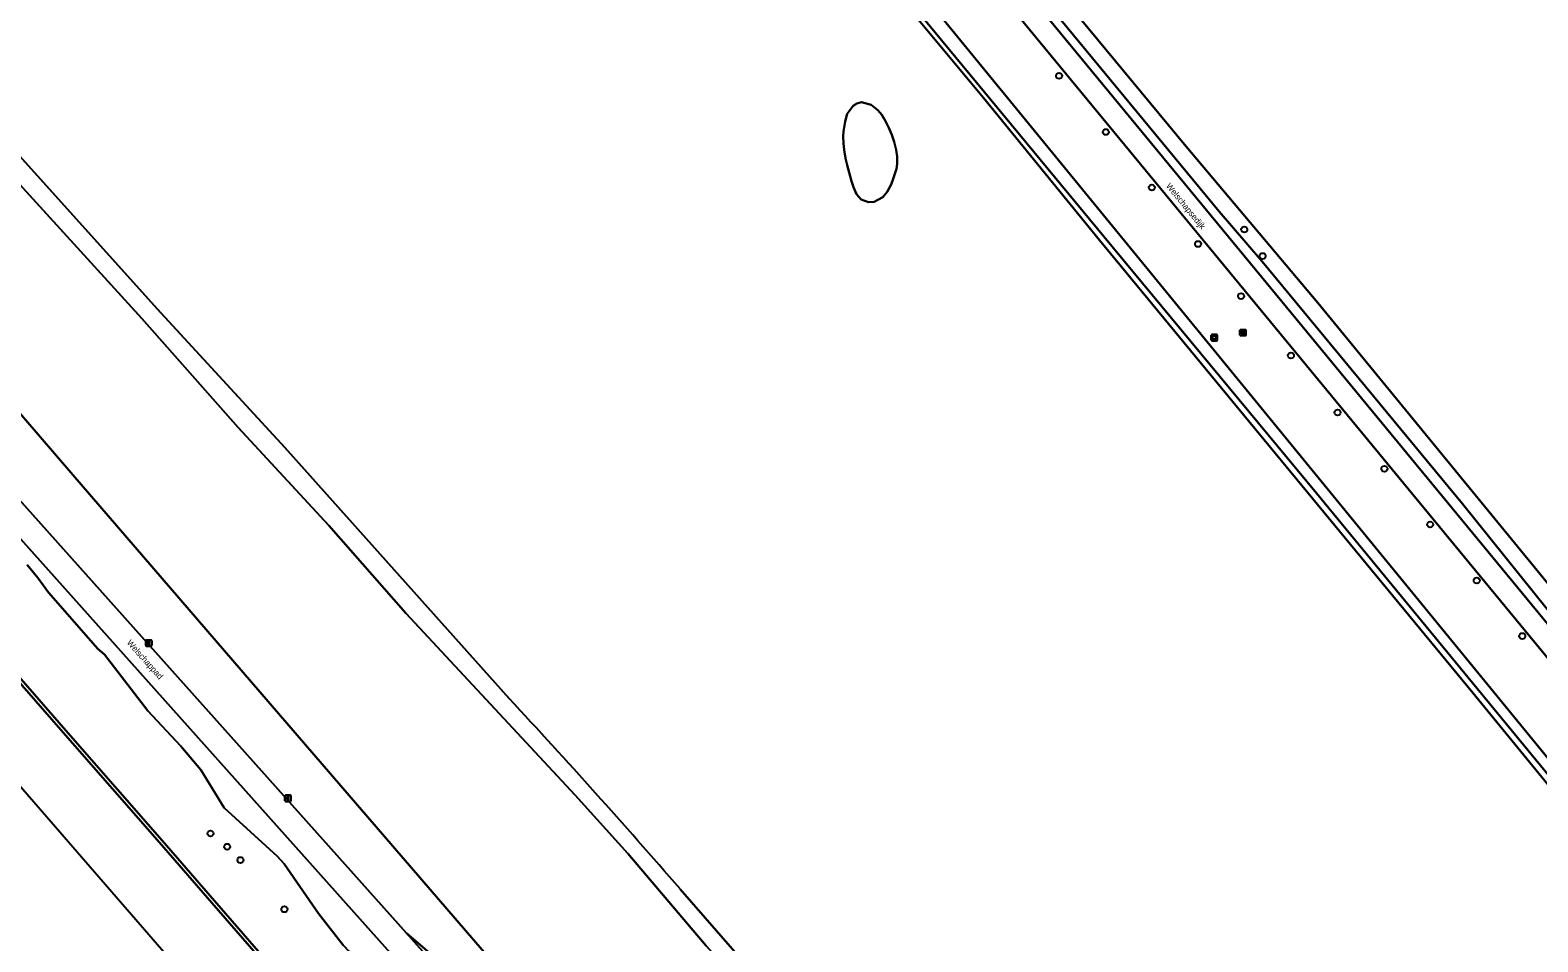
# Model space of a CAD drawing. Extents: x 156061 to 157804, y 383437 to 385640.
# Drawn here: x 156563.1 to 156810.9, y 384752.9 to 384902.7 of the extents above; entities that cross this region are included whole.
import ezdxf

# ---------------------------------------------------------------- set-up
doc = ezdxf.new("R2010")
doc.units = 0
for name, color, linetype in [('IMGEO_Berm_groen', 7, 'Continuous'), ('IMGEO_Boom', 7, 'Continuous'), ('IMGEO_Fietspad_gesloten', 7, 'Continuous'), ('IMGEO_Gemengd_bos', 7, 'Continuous'), ('IMGEO_Grasland_overig', 7, 'Continuous'), ('IMGEO_Groenvoorziening', 7, 'Continuous'), ('IMGEO_Kademuur', 7, 'Continuous'), ('IMGEO_Lichtmast', 7, 'Continuous'), ('IMGEO_Loofbos', 7, 'Continuous'), ('IMGEO_Meer_plas_ven_vijver', 7, 'Continuous'), ('IMGEO_Openbare_ruimte_label', 7, 'Continuous'), ('IMGEO_Rioolput', 7, 'Continuous'), ('IMGEO_Verklikker', 7, 'Continuous'), ('IMGEO_Waterloop', 7, 'Continuous')]:
    doc.layers.add(name, color=color, linetype=linetype)

msp = doc.modelspace()

# ---------------------------------------------------------------- linework, layer by layer
at = {"layer": 'IMGEO_Berm_groen'}
for points in [[(156600.26, 385062.64), (156611.41, 385049.1), (156616.13, 385043.37), (156628.31, 385028.6), (156628.66, 385028.19), (156634.53, 385021.05), (156651.9, 385000), (156717.24, 384920.7), (156766.23, 384861.24), (156857.95, 384750), (156913.26, 384682.92), (156945.25, 384644.12), (156951.65, 384636.45), (156952.01, 384636.1)], [(156825.25, 384792.4), (156814.89, 384804.47), (156798.51, 384824.86), (156765.57, 384864.69), (156758.53, 384872.88), (156724.2, 384914.5), (156722.65, 384916.11)]]:
    msp.add_lwpolyline(points, dxfattribs=at)
at = {"layer": 'IMGEO_Boom'}
for centre in [(156732.21, 384895.16), (156739.9, 384885.94), (156747.46, 384876.81), (156762.65, 384869.91), (156755.05, 384867.54), (156765.66, 384865.56), (156762.12, 384858.98), (156770.32, 384849.21), (156777.98, 384839.85), (156785.67, 384830.6), (156793.2, 384821.46), (156800.84, 384812.24), (156808.33, 384803.12), (156592.79, 384770.69), (156595.52, 384768.51), (156597.7, 384766.32), (156604.92, 384758.23)]:
    msp.add_circle(centre, 0.489, dxfattribs=at)
at = {"layer": 'IMGEO_Fietspad_gesloten'}
for points in [[(156913.26, 384682.92), (156857.95, 384750), (156766.23, 384861.24), (156717.24, 384920.7), (156651.9, 385000), (156634.53, 385021.05), (156628.66, 385028.19), (156628.31, 385028.6), (156616.13, 385043.37), (156611.41, 385049.1), (156600.26, 385062.64)], [(156605.09, 385050.03), (156608.82, 385046.51), (156609.37, 385045.98), (156609.93, 385045.44), (156647.34, 385000), (156714.45, 384918.5), (156763.61, 384858.81), (156853.32, 384750), (156910.52, 384680.62), (156937.97, 384647.33)], [(156389.78, 385020.78), (156386.85, 385017.71), (156440.03, 384956.66), (156474.46, 384917.12), (156506.69, 384880.33), (156537.77, 384845.66), (156649.72, 384720.32), (156655.93, 384713.48)], [(156658.08, 384717.36), (156637.43, 384740.32), (156624.97, 384754.31), (156558.57, 384828.68), (156512.76, 384879.85), (156490.45, 384905.14), (156389.78, 385020.78)]]:
    msp.add_lwpolyline(points, dxfattribs=at)
at = {"layer": 'IMGEO_Gemengd_bos'}
for points in [[(156396.32, 385031.8), (156570.16, 384829.59), (156729.94, 384644.21), (156782.31, 384583.04)], [(156780.11, 384627.13), (156746.84, 384665.42), (156737.6, 384676.85), (156728.37, 384688.78), (156722.78, 384695.21), (156722.52, 384694.99), (156717.59, 384701.16), (156707.45, 384713.85), (156682.3, 384743.46), (156676.27, 384750), (156674.23, 384752.22), (156661.34, 384767.38), (156652.69, 384776.96), (156624.88, 384806.9), (156612.2, 384821.29), (156597.34, 384837.38), (156581.52, 384855.31), (156560.26, 384878.65)]]:
    msp.add_lwpolyline(points, dxfattribs=at)
at = {"layer": 'IMGEO_Grasland_overig'}
for points in [[(156570.16, 384829.59), (156396.32, 385031.8), (156379.93, 385052.11), (156377.42, 385051.32), (156377.51, 385050.41), (156377.73, 385048.43)], [(156389.78, 385020.78), (156490.45, 384905.14), (156512.76, 384879.85), (156558.57, 384828.68), (156624.97, 384754.31), (156642.45, 384739.35), (156650.27, 384729.18), (156661.68, 384716.56), (156667.31, 384711.79), (156673.65, 384706.04)], [(156641.88, 384792.84), (156605.01, 384834.13), (156584.04, 384856.9), (156559.92, 384883.67)], [(156560.26, 384878.65), (156581.52, 384855.31), (156597.34, 384837.38), (156612.2, 384821.29), (156624.88, 384806.9), (156652.69, 384776.96), (156661.34, 384767.38), (156674.23, 384752.22), (156676.27, 384750), (156682.3, 384743.46), (156707.45, 384713.85), (156717.59, 384701.16), (156722.52, 384694.99), (156722.78, 384695.21), (156723.59, 384695.9)], [(156819.55, 384603.95), (156819.58, 384607.25), (156818.29, 384610.77), (156816.59, 384609.73), (156815.93, 384604.93), (156809.77, 384601.71), (156807.27, 384598.54), (156803.41, 384595.58), (156782.31, 384583.04), (156729.94, 384644.21), (156570.16, 384829.59)], [(156699.29, 384727.88), (156680.01, 384750), (156669.93, 384761.56)]]:
    msp.add_lwpolyline(points, dxfattribs=at)
msp.add_arc((155746.23, 383961.3), 1222.15, 40.90464, 42.87435, dxfattribs=at)
at = {"layer": 'IMGEO_Groenvoorziening'}
for points in [[(156719.79, 384891.58), (156704.18, 384910.35), (156680.54, 384938.81), (156675.71, 384944.62), (156664.3, 384958.48), (156630.11, 385000), (156603.33, 385032.02), (156590.03, 385048.18), (156581.38, 385058.42), (156579.11, 385060.99), (156576.25, 385063.65), (156574.17, 385065.13), (156572.59, 385066.26), (156568.65, 385068.4), (156563.11, 385070.71)], [(156655.93, 384713.48), (156649.72, 384720.32), (156537.77, 384845.66), (156506.69, 384880.33), (156474.46, 384917.12), (156440.03, 384956.66), (156386.85, 385017.71)], [(156704.18, 384910.35), (156719.79, 384891.58), (156738.88, 384868.16), (156800.19, 384793.8), (156826.08, 384762.21), (156836.09, 384750), (156844.21, 384740.36), (156850.94, 384732.38), (156863, 384717.8), (156900.59, 384672.36), (156906.38, 384677.17), (156910.52, 384680.62), (156853.32, 384750), (156763.61, 384858.81), (156714.45, 384918.5)], [(156706.71, 384912.4), (156835.46, 384755.03), (156834.95, 384754.67), (156834.17, 384754.1), (156774.54, 384826.62), (156739.56, 384868.75), (156704.8, 384910.9)], [(156826.08, 384762.21), (156800.19, 384793.8), (156738.88, 384868.16), (156719.79, 384891.58)], [(156559.92, 384883.67), (156584.04, 384856.9), (156605.01, 384834.13), (156641.88, 384792.84)], [(156562.67, 384814.85), (156564.43, 384812.71), (156566.18, 384810.28), (156574.27, 384801.02), (156575.34, 384800.07), (156582.49, 384790.82), (156587.88, 384785.05), (156591.18, 384781.13), (156595, 384774.88), (156603.76, 384766.96), (156604.88, 384765.67), (156610.54, 384757.56), (156614.58, 384752.31), (156615.57, 384751.27), (156617.73, 384750), (156618.89, 384748.8)], [(156669.93, 384761.56), (156680.01, 384750), (156699.29, 384727.88)], [(156642.45, 384739.35), (156624.97, 384754.31), (156637.43, 384740.32), (156658.08, 384717.36)]]:
    msp.add_lwpolyline(points, dxfattribs=at)
msp.add_lwpolyline([(156697.05, 384887.68), (156697.37, 384888.95), (156698.37, 384890.26), (156698.97, 384890.63), (156699.76, 384890.84), (156701.32, 384890.43), (156702.45, 384889.52), (156703.07, 384888.74), (156703.69, 384887.73), (156704.27, 384886.61), (156704.75, 384885.48), (156705.14, 384884.33), (156705.44, 384883.03), (156705.59, 384881.91), (156705.6, 384880.69), (156705.49, 384879.87), (156704.86, 384877.92), (156704.55, 384877.19), (156703.97, 384876.11), (156703.26, 384875.26), (156701.85, 384874.47), (156700.89, 384874.43), (156699.71, 384874.86), (156698.93, 384875.71), (156698.43, 384876.86), (156698.13, 384877.87), (156697.73, 384879.31), (156697.42, 384880.49), (156697.15, 384881.65), (156696.91, 384883.02), (156696.79, 384884.04), (156696.75, 384885.26), (156696.79, 384886.02)], close=True, dxfattribs=at)
msp.add_arc((155746.23, 383961.3), 1222.15, 40.90464, 42.87435, dxfattribs=at)
at = {"layer": 'IMGEO_Kademuur'}
msp.add_lwpolyline([(156547.18, 384811.77), (156568.98, 384786.82), (156584.4, 384769.18), (156593.02, 384759.27), (156604.27, 384746.32), (156619.34, 384728.85), (156628.51, 384718.21), (156637.24, 384708.07), (156637.61, 384708.4), (156628.92, 384718.57), (156619.76, 384729.21), (156604.69, 384746.67), (156593.43, 384759.63), (156584.82, 384769.54), (156569.39, 384787.18), (156547.59, 384812.13)], dxfattribs=at)
at = {"layer": 'IMGEO_Lichtmast'}
for p, q in [((156582.13, 384801.56), (156582.13, 384802.35)), ((156582.13, 384802.35), (156582.13, 384801.56)), ((156582.23, 384802.45), (156583.02, 384802.45)), ((156583.02, 384802.45), (156582.23, 384802.45)), ((156583.02, 384801.46), (156582.23, 384801.46)), ((156582.23, 384801.46), (156583.02, 384801.46)), ((156583.12, 384802.35), (156583.12, 384801.56)), ((156583.12, 384801.56), (156583.12, 384802.35)), ((156605, 384776.06), (156605, 384776.86)), ((156605, 384776.86), (156605, 384776.06)), ((156605.1, 384776.96), (156605.89, 384776.96)), ((156605.89, 384776.96), (156605.1, 384776.96)), ((156605.99, 384776.86), (156605.99, 384776.06)), ((156605.99, 384776.06), (156605.99, 384776.86)), ((156605.89, 384775.96), (156605.1, 384775.96)), ((156605.1, 384775.96), (156605.89, 384775.96))]:
    msp.add_line(p, q, dxfattribs=at)
for points in [[(156582.55, 384802.33), (156582.7, 384802.33), (156582.7, 384801.58), (156582.55, 384801.58), (156582.55, 384802.33)], [(156605.42, 384776.83), (156605.57, 384776.83), (156605.57, 384776.08), (156605.42, 384776.08), (156605.42, 384776.83)]]:
    msp.add_lwpolyline(points, dxfattribs=at)
for centre, start, end in [((156582.23, 384802.35), 90, 180), ((156582.23, 384802.35), 90, 180), ((156582.23, 384801.56), 180, 270), ((156582.23, 384801.56), 180, 270), ((156583.02, 384802.35), 0, 90), ((156583.02, 384802.35), 360, 90), ((156583.02, 384801.56), 270, 0), ((156583.02, 384801.56), 270, 0), ((156605.1, 384776.86), 90, 180), ((156605.1, 384776.86), 90, 180), ((156605.89, 384776.86), 0, 90), ((156605.89, 384776.86), 360, 90), ((156605.1, 384776.06), 180, 270), ((156605.1, 384776.06), 180, 270), ((156605.89, 384776.06), 270, 0), ((156605.89, 384776.06), 270, 0)]:
    msp.add_arc(centre, 0.1, start, end, dxfattribs=at)
at = {"layer": 'IMGEO_Loofbos'}
for points in [[(156725.37, 384917.08), (156753.08, 384883.55), (156774.76, 384857.86), (156826.96, 384794.18)], [(156618.89, 384748.8), (156617.73, 384750), (156615.57, 384751.27), (156614.58, 384752.31), (156610.54, 384757.56), (156604.88, 384765.67), (156603.76, 384766.96), (156595, 384774.88), (156591.18, 384781.13), (156587.88, 384785.05), (156582.49, 384790.82), (156575.34, 384800.07), (156574.27, 384801.02), (156566.18, 384810.28), (156564.43, 384812.71), (156562.67, 384814.85)], [(156547.59, 384812.13), (156569.39, 384787.18), (156584.82, 384769.54), (156593.43, 384759.63), (156604.69, 384746.67), (156619.76, 384729.21), (156628.92, 384718.57), (156637.61, 384708.4), (156643.51, 384701.65), (156643.8, 384701.87), (156644.2, 384702.03), (156644.83, 384701.98), (156645.41, 384701.56), (156646.25, 384700.63), (156650.66, 384695.65), (156650.36, 384695.39), (156650.2, 384694.86), (156649.86, 384694.28), (156652.69, 384690.99), (156659.35, 384683.21), (156676.83, 384663.11), (156693, 384644.5), (156705.28, 384630.41)]]:
    msp.add_lwpolyline(points, dxfattribs=at)
at = {"layer": 'IMGEO_Meer_plas_ven_vijver'}
msp.add_lwpolyline([(156697.05, 384887.68), (156696.79, 384886.02), (156696.75, 384885.26), (156696.79, 384884.04), (156696.91, 384883.02), (156697.15, 384881.65), (156697.42, 384880.49), (156697.73, 384879.31), (156698.13, 384877.87), (156698.43, 384876.86), (156698.93, 384875.71), (156699.71, 384874.86), (156700.89, 384874.43), (156701.85, 384874.47), (156703.26, 384875.26), (156703.97, 384876.11), (156704.55, 384877.19), (156704.86, 384877.92), (156705.49, 384879.87), (156705.6, 384880.69), (156705.59, 384881.91), (156705.44, 384883.03), (156705.14, 384884.33), (156704.75, 384885.48), (156704.27, 384886.61), (156703.69, 384887.73), (156703.07, 384888.74), (156702.45, 384889.52), (156701.32, 384890.43), (156699.76, 384890.84), (156698.97, 384890.63), (156698.37, 384890.26), (156697.37, 384888.95)], close=True, dxfattribs=at)
at = {"layer": 'IMGEO_Rioolput'}
for p, q in [((156761.93, 384852.55), (156761.93, 384853.4)), ((156762, 384853.47), (156762.86, 384853.47)), ((156762.93, 384853.4), (156762.93, 384852.55)), ((156762.86, 384852.47), (156762, 384852.47)), ((156762.19, 384852.97), (156762.19, 384852.98)), ((156762.23, 384853.02), (156762.63, 384853.02)), ((156762.63, 384852.93), (156762.23, 384852.93)), ((156762.42, 384853.25), (156762.44, 384853.25)), ((156762.44, 384852.69), (156762.42, 384852.69)), ((156762.67, 384852.98), (156762.67, 384852.97))]:
    msp.add_line(p, q, dxfattribs=at)
for points in [[(156761.93, 384852.55), (156761.93, 384853.4)], [(156762, 384853.47), (156762.86, 384853.47)], [(156762.93, 384853.4), (156762.93, 384852.55)], [(156762.86, 384852.47), (156762, 384852.47)]]:
    msp.add_lwpolyline(points, dxfattribs=at)
for centre, radius, start, end in [((156762.01, 384853.4), 0.0765, 91.552, 178.448), ((156762.01, 384853.4), 0.0765, 91.552, 178.448), ((156762.85, 384853.4), 0.0765, 1.552, 88.448), ((156762.85, 384853.4), 0.0765, 1.552, 88.448), ((156762.01, 384852.55), 0.0765, 181.552, 268.448), ((156762.01, 384852.55), 0.0765, 181.552, 268.448), ((156762.23, 384852.98), 0.0403, 85.8775, 175.7526), ((156762.23, 384852.97), 0.0366, 178.938, 274.7102), ((156762.63, 384852.98), 0.0386, 1.7309, 96.639), ((156762.63, 384852.97), 0.043, 264.8664, 352.4533), ((156762.85, 384852.55), 0.0765, 271.552, 358.448), ((156762.85, 384852.55), 0.0765, 271.552, 358.448)]:
    msp.add_arc(centre, radius, start, end, dxfattribs=at)
for centre, major_axis, ratio, start_param, end_param in [((156762.42, 384852.97), (-0.387, 0.002), 0.722429, 4.712389, 7.853982), ((156762.44, 384852.97), (-0.39, 0.002), 0.717154, 1.570796, 4.712389)]:
    msp.add_ellipse(centre, major_axis=major_axis, ratio=ratio, start_param=start_param, end_param=end_param, dxfattribs=at)
at = {"layer": 'IMGEO_Verklikker'}
for p, q in [((156757.21, 384851.75), (156757.21, 384852.55)), ((156757.21, 384852.55), (156757.21, 384851.75)), ((156757.31, 384852.65), (156758.1, 384852.65)), ((156758.1, 384852.65), (156757.31, 384852.65)), ((156758.1, 384851.65), (156757.31, 384851.65)), ((156757.31, 384851.65), (156758.1, 384851.65)), ((156758.2, 384852.55), (156758.2, 384851.75)), ((156758.2, 384851.75), (156758.2, 384852.55))]:
    msp.add_line(p, q, dxfattribs=at)
for points in [[(156757.31, 384852.38), (156758.09, 384852.38), (156758.09, 384851.92), (156757.31, 384851.92), (156757.31, 384852.38)], [(156757.37, 384852.32), (156757.37, 384851.98), (156758.03, 384851.98), (156758.03, 384852.32), (156757.37, 384852.32)]]:
    msp.add_lwpolyline(points, dxfattribs=at)
for centre, start, end in [((156757.31, 384852.55), 90, 180), ((156757.31, 384852.55), 90, 180), ((156757.31, 384851.75), 180, 270), ((156757.31, 384851.75), 180, 270), ((156758.1, 384852.55), 0, 90), ((156758.1, 384852.55), 360, 90), ((156758.1, 384851.75), 270, 0), ((156758.1, 384851.75), 270, 0)]:
    msp.add_arc(centre, 0.1, start, end, dxfattribs=at)
at = {"layer": 'IMGEO_Waterloop'}
for points in [[(156069.34, 385360.86), (156061.16, 385355.59), (156648.24, 384678.4), (156868.63, 384425.31)], [(156722.65, 384916.11), (156724.2, 384914.5), (156758.53, 384872.88), (156765.57, 384864.69), (156798.51, 384824.86), (156814.89, 384804.47), (156825.25, 384792.4)], [(156774.76, 384857.86), (156753.08, 384883.55), (156725.37, 384917.08)], [(156826.96, 384794.18), (156774.76, 384857.86)], [(156704.9, 384630.08), (156692.62, 384644.17), (156676.45, 384662.79), (156658.97, 384682.89), (156652.31, 384690.66), (156646.93, 384696.92), (156647.31, 384697.24), (156648.62, 384695.72), (156649.17, 384696.73), (156646.01, 384700.3), (156645.24, 384699.67), (156646.4, 384698.34), (156646.03, 384698.02), (156637.24, 384708.07), (156628.51, 384718.21), (156619.34, 384728.85), (156604.27, 384746.32), (156593.02, 384759.27), (156584.4, 384769.18), (156568.98, 384786.82), (156547.18, 384811.77)]]:
    msp.add_lwpolyline(points, dxfattribs=at)
msp.add_lwpolyline([(156706.71, 384912.4), (156697.98, 384923.07), (156680.72, 384943.26), (156679.88, 384942.66), (156679.07, 384942.09), (156704.8, 384910.9), (156739.56, 384868.75), (156774.54, 384826.62), (156834.17, 384754.1), (156834.95, 384754.67), (156835.46, 384755.03)], close=True, dxfattribs=at)

# ---------------------------------------------------------------- texts
at = {"layer": 'IMGEO_Openbare_ruimte_label'}
for s, rotation, p in [('Welschapsedijk', 309.1967, (156749.72, 384877.04)), ('Welschappad', 311.7572, (156578.95, 384801.96))]:
    msp.add_text(s, height=1, rotation=rotation, dxfattribs=at).set_placement(p)

doc.saveas('drawing.dxf')
